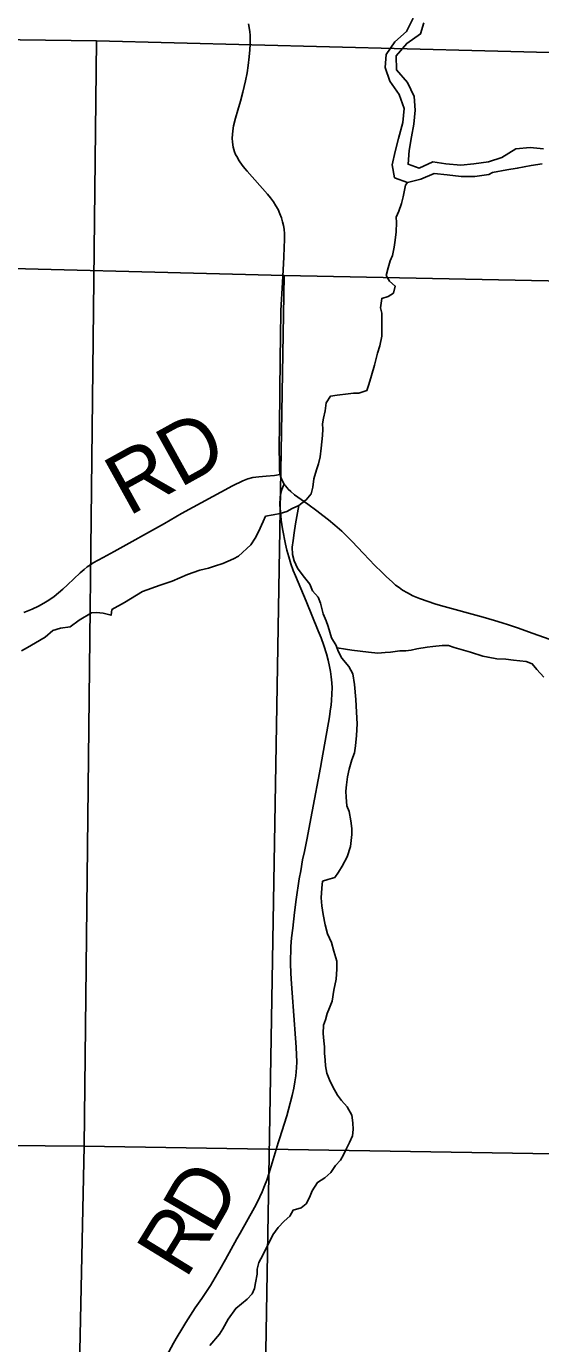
# Model space of a CAD drawing. Extents: x -19.9 to 41.9, y 0 to 32.3.
# Drawn here: x 5.786 to 6.268, y 15.736 to 16.969 of the extents above; entities that cross this region are included whole.
import ezdxf

# ---------------------------------------------------------------- set-up
doc = ezdxf.new("R2010")
doc.units = 0
for name, color, linetype in [('GM_X_Corporation', 7, 'Continuous'), ('GM_X_County_Road', 7, 'Continuous'), ('GM_X_Major_River', 7, 'Continuous'), ('GM_X_Minor_River', 7, 'Continuous'), ('GM_X_Section', 7, 'Continuous'), ('GM_X_Township_Road', 7, 'Continuous'), ('GM_X_Township_Road_Text', 7, 'Continuous')]:
    doc.layers.add(name, color=color, linetype=linetype)

msp = doc.modelspace()

# ---------------------------------------------------------------- linework, layer by layer
at = {"layer": 'GM_X_Corporation'}
for points in [[(5.0171, 16.9663), (5.8519, 16.9554), (5.8404, 15.9209), (5.0026, 15.928), (5.0159, 16.8409)], [(5.8519, 16.9554), (6.8696, 16.9292), (6.8522, 15.9041), (5.8404, 15.9209)], [(5.8404, 15.9209), (5.8188, 14.9036), (4.9872, 14.9075), (5.0009, 15.8404), (5.0026, 15.928)], [(6.8522, 15.9041), (6.8226, 14.894), (5.8188, 14.9036), (5.8404, 15.9209)]]:
    msp.add_lwpolyline(points, close=True, dxfattribs=at)
at = {"layer": 'GM_X_County_Road'}
msp.add_lwpolyline([(5.9943, 16.9715), (5.995, 16.968), (5.9956, 16.9639), (5.9958, 16.9607), (5.9958, 16.9572), (5.9957, 16.9525), (5.9954, 16.9472), (5.9948, 16.9404), (5.9939, 16.9324), (5.993, 16.9257), (5.9914, 16.9182), (5.9889, 16.9074), (5.9866, 16.8989), (5.9843, 16.8906), (5.9821, 16.883), (5.9803, 16.876), (5.9795, 16.8711), (5.9792, 16.8677), (5.9791, 16.8645), (5.9793, 16.8605), (5.98, 16.8561), (5.9804, 16.8539), (5.9811, 16.8516), (5.9822, 16.849), (5.9832, 16.8471), (5.9855, 16.8431), (5.9882, 16.8391), (5.9907, 16.8361), (5.9929, 16.8335), (6.0119, 16.812), (6.0148, 16.8084), (6.0175, 16.8047), (6.0198, 16.8011), (6.0219, 16.7975), (6.0237, 16.7936), (6.0251, 16.7898), (6.0262, 16.7862), (6.027, 16.7826), (6.0275, 16.7791), (6.0278, 16.7749), (6.0279, 16.7693), (6.0276, 16.7622), (6.0273, 16.7531), (6.0261, 16.7294), (6.0246, 16.7032), (6.0241, 16.6775), (6.0239, 16.659), (6.0236, 16.6257), (6.0232, 16.5947), (6.0229, 16.576), (6.0232, 16.5582), (6.0234, 16.5537), (6.0237, 16.5506), (6.0239, 16.5494), (6.0243, 16.5478), (6.0251, 16.5454), (6.0264, 16.5427), (6.0277, 16.5405), (6.0283, 16.5397), (6.029, 16.5388), (6.0305, 16.537), (6.0315, 16.5358), (6.0338, 16.5336), (6.0374, 16.5306), (6.0434, 16.5262), (6.0499, 16.5217), (6.0583, 16.5155), (6.0637, 16.5111), (6.0692, 16.507), (6.0749, 16.5021), (6.0815, 16.4964), (6.0909, 16.4871), (6.102, 16.4755), (6.1124, 16.4645), (6.119, 16.458), (6.1231, 16.4539), (6.1289, 16.4487), (6.1319, 16.446), (6.1351, 16.4436), (6.1383, 16.4414), (6.1429, 16.4387), (6.148, 16.4361), (6.1543, 16.4335), (6.1624, 16.4306), (6.1687, 16.4286), (6.1738, 16.427), (6.214, 16.4159), (6.2192, 16.4145), (6.2246, 16.4129), (6.2317, 16.4107), (6.2377, 16.4087), (6.246, 16.406), (6.2608, 16.4008), (6.2755, 16.3954)], dxfattribs=at)
at = {"layer": 'GM_X_Major_River'}
for points in [[(6.1484, 16.9767), (6.1421, 16.9641), (6.1313, 16.9545), (6.123, 16.9426)], [(6.1327, 16.9283), (6.1325, 16.9416), (6.1423, 16.9531), (6.1551, 16.9619), (6.1584, 16.9722)], [(6.123, 16.9426), (6.122, 16.9304), (6.1264, 16.9176), (6.1353, 16.9052), (6.14, 16.8923), (6.1386, 16.879), (6.1346, 16.8642), (6.1314, 16.852), (6.1288, 16.8395), (6.1309, 16.8273), (6.1431, 16.8229), (6.1556, 16.8261), (6.1681, 16.8312), (6.1802, 16.8302), (6.1932, 16.8285), (6.2061, 16.8286), (6.2193, 16.8303)], [(6.2703, 16.8544), (6.2578, 16.8558), (6.2445, 16.8545), (6.2313, 16.8464), (6.2188, 16.8421), (6.2052, 16.8404), (6.193, 16.8391), (6.179, 16.8404), (6.1668, 16.8422), (6.1539, 16.8363), (6.1436, 16.84), (6.1446, 16.8529), (6.1468, 16.8655), (6.1489, 16.8776), (6.1503, 16.8906), (6.1493, 16.9034), (6.1431, 16.9166), (6.1327, 16.9283)], [(6.2193, 16.8303), (6.2227, 16.8322), (6.236, 16.8347), (6.2458, 16.8363), (6.2587, 16.8387), (6.269, 16.8404)]]:
    msp.add_lwpolyline(points, dxfattribs=at)
at = {"layer": 'GM_X_Minor_River'}
for points in [[(6.1431, 16.8229), (6.1412, 16.8205), (6.1391, 16.8094), (6.1373, 16.8033), (6.1348, 16.796), (6.1326, 16.7903), (6.1327, 16.7854), (6.1324, 16.7766), (6.1314, 16.769), (6.1307, 16.7625), (6.1289, 16.7545), (6.1267, 16.7495), (6.1249, 16.743), (6.1231, 16.7357), (6.1262, 16.7304), (6.1316, 16.7259), (6.1298, 16.7194), (6.1249, 16.7163), (6.1189, 16.7143), (6.1179, 16.7056), (6.1191, 16.7006), (6.1189, 16.6911), (6.119, 16.6789), (6.1173, 16.6701), (6.1151, 16.6632), (6.1122, 16.6518), (6.1093, 16.6422), (6.1068, 16.6338), (6.105, 16.6281), (6.0975, 16.6257), (6.0925, 16.6256), (6.0876, 16.6251), (6.0771, 16.6238), (6.071, 16.623), (6.0669, 16.6165), (6.0659, 16.6092), (6.0645, 16.6023), (6.0634, 16.597), (6.0639, 16.592), (6.0636, 16.5859), (6.0629, 16.5802), (6.0622, 16.5741), (6.0612, 16.5661), (6.0598, 16.5596), (6.058, 16.5539), (6.0555, 16.5455), (6.0544, 16.5378), (6.053, 16.5313), (6.0482, 16.5259), (6.0414, 16.5205), (6.035, 16.5178), (6.0302, 16.515), (6.0238, 16.513), (6.0173, 16.5118), (6.0102, 16.5105), (6.008, 16.5055), (6.0036, 16.496), (6.0006, 16.4898), (5.9965, 16.4837), (5.985, 16.4732), (5.9801, 16.4705), (5.9703, 16.4661), (5.9624, 16.4637), (5.9567, 16.4618), (5.9488, 16.4601), (5.9371, 16.4558), (5.9228, 16.4498), (5.9115, 16.4459), (5.895, 16.4399), (5.8781, 16.4297), (5.8664, 16.4231), (5.8657, 16.4178), (5.8581, 16.4196), (5.8521, 16.4202), (5.8472, 16.4201), (5.8359, 16.4131), (5.8273, 16.4069), (5.8182, 16.4056), (5.811, 16.4036), (5.8039, 16.3974), (5.7949, 16.392), (5.7874, 16.3877), (5.7818, 16.3845)], [(6.0414, 16.5205), (6.0383, 16.5033), (6.0369, 16.4949), (6.0359, 16.4877), (6.0352, 16.4816), (6.0353, 16.4747), (6.0369, 16.4687), (6.04, 16.4619), (6.0454, 16.4547), (6.0516, 16.4468), (6.054, 16.4407), (6.0593, 16.4347), (6.0617, 16.4291), (6.0641, 16.4192), (6.0669, 16.4124), (6.0688, 16.4071), (6.072, 16.3965), (6.0763, 16.3893), (6.0782, 16.384), (6.0817, 16.3776), (6.0883, 16.3697), (6.0918, 16.3629), (6.0935, 16.353), (6.0948, 16.3389), (6.0953, 16.3271), (6.0959, 16.3161), (6.0953, 16.3051), (6.0943, 16.2955), (6.0936, 16.2891), (6.0911, 16.2825), (6.0885, 16.2737), (6.0868, 16.2665), (6.0861, 16.2589), (6.0854, 16.2531), (6.0855, 16.2474), (6.0864, 16.2395), (6.0884, 16.2341), (6.09, 16.2254), (6.0909, 16.2182), (6.0909, 16.2125), (6.0896, 16.2014), (6.0867, 16.1915), (6.0819, 16.183), (6.0786, 16.1773), (6.0749, 16.1723), (6.0685, 16.1703), (6.0636, 16.1687), (6.0629, 16.1622), (6.0623, 16.1531), (6.0628, 16.1458), (6.064, 16.1375), (6.066, 16.128), (6.0681, 16.1196), (6.072, 16.1113), (6.074, 16.1034), (6.0768, 16.0939), (6.0769, 16.0866), (6.0763, 16.0771), (6.0741, 16.0668), (6.0724, 16.0565), (6.0702, 16.0504), (6.068, 16.045), (6.0662, 16.0389), (6.0644, 16.0339), (6.0641, 16.0263), (6.0646, 16.0195), (6.0654, 16.0138), (6.0655, 16.0077), (6.066, 16.0012), (6.0664, 15.9959), (6.0677, 15.9891), (6.07, 15.983), (6.0732, 15.9762), (6.0774, 15.9686), (6.0813, 15.9634), (6.0867, 15.9577), (6.091, 15.9498), (6.0918, 15.9426), (6.0923, 15.9365), (6.0916, 15.9304), (6.0887, 15.9243), (6.0861, 15.9185), (6.0832, 15.9128), (6.0802, 15.9078), (6.0758, 15.9028), (6.0713, 15.8962), (6.0657, 15.8912), (6.0589, 15.8869), (6.0538, 15.8788), (6.0512, 15.8727), (6.0483, 15.8669), (6.0434, 15.8631), (6.0359, 15.8607), (6.0329, 15.8553), (6.0277, 15.8507), (6.0221, 15.8445), (6.0169, 15.8379), (6.0077, 15.8188), (6.004, 15.8119), (6.0022, 15.8057), (6.0023, 15.8008)], [(6.0771, 16.3872), (6.085, 16.386), (6.0911, 16.385), (6.0987, 16.3843), (6.1066, 16.3833), (6.1154, 16.3823), (6.1222, 16.3828), (6.1271, 16.3832), (6.1358, 16.3845), (6.1415, 16.3846), (6.1464, 16.385), (6.1517, 16.3862), (6.1615, 16.3879), (6.1668, 16.3884), (6.1755, 16.3893), (6.1815, 16.3893), (6.1868, 16.3875), (6.2021, 16.3832), (6.2135, 16.3795), (6.2184, 16.3785), (6.2268, 16.3771), (6.2351, 16.3768), (6.2423, 16.3758), (6.254, 16.3744), (6.2598, 16.3722), (6.264, 16.367), (6.2705, 16.3598)], [(6.0023, 15.8008), (6.0009, 15.7928), (5.9998, 15.7874), (5.9976, 15.7824), (5.9931, 15.7774), (5.9823, 15.7689), (5.9752, 15.7589), (5.9701, 15.7497), (5.9671, 15.7447), (5.9582, 15.7343)]]:
    msp.add_lwpolyline(points, dxfattribs=at)
at = {"layer": 'GM_X_Section'}
for points in [[(5.0099, 16.7619), (6.0276, 16.7357), (6.0103, 15.7106), (4.9984, 15.7274)], [(6.0276, 16.7357), (7.0463, 16.7153), (7.0239, 15.7019), (6.0103, 15.7106)]]:
    msp.add_lwpolyline(points, close=True, dxfattribs=at)
at = {"layer": 'GM_X_Township_Road'}
for points in [[(5.7841, 16.4202), (5.7917, 16.4234), (5.7977, 16.4262), (5.8028, 16.429), (5.8073, 16.4318), (5.8125, 16.4353), (5.8165, 16.4389), (5.8204, 16.4422), (5.8247, 16.4464), (5.8367, 16.4575), (5.8404, 16.4607), (5.8434, 16.463), (5.8463, 16.465), (5.849, 16.4667), (5.8582, 16.4718), (5.8685, 16.4774), (5.9156, 16.5038), (5.9316, 16.5129), (5.9794, 16.5388), (5.989, 16.5437), (5.9937, 16.5454), (5.9984, 16.5466), (6.0038, 16.5475), (6.0107, 16.5481), (6.0185, 16.5487), (6.0239, 16.5494)], [(5.9128, 15.7153), (5.9241, 15.7364), (5.9266, 15.7408), (5.9327, 15.7511), (5.9356, 15.7556), (5.9442, 15.7693), (5.9505, 15.7781), (5.9586, 15.7904), (5.9632, 15.7978), (5.9675, 15.8053), (5.9726, 15.8147), (5.9832, 15.8339), (5.9863, 15.8392), (5.9999, 15.8634), (6.0028, 15.8688), (6.0069, 15.8779), (6.0092, 15.8836), (6.0113, 15.8889), (6.0136, 15.8958), (6.0219, 15.924), (6.0231, 15.9276), (6.03, 15.9493), (6.0317, 15.9551), (6.0351, 15.9681), (6.0366, 15.9751), (6.0377, 15.9809), (6.0385, 15.9866), (6.0392, 15.9941), (6.0395, 15.9998), (6.0392, 16.0063), (6.0388, 16.0134), (6.0382, 16.022), (6.0351, 16.0643), (6.0345, 16.0726), (6.034, 16.0823), (6.0336, 16.0922), (6.0338, 16.1077), (6.0345, 16.1157), (6.0356, 16.1247), (6.0374, 16.1394), (6.0389, 16.1517), (6.0418, 16.1709), (6.0431, 16.1784), (6.0448, 16.1887), (6.0465, 16.1966), (6.0488, 16.2075), (6.0538, 16.234), (6.0616, 16.2754), (6.0628, 16.2823), (6.0699, 16.3226), (6.0707, 16.328), (6.0715, 16.3339), (6.0718, 16.338), (6.0723, 16.3443), (6.0724, 16.3497), (6.0722, 16.3545), (6.0717, 16.36), (6.071, 16.3652), (6.0702, 16.3697), (6.0688, 16.3756), (6.0672, 16.3818), (6.0649, 16.3893), (6.0623, 16.3965), (6.0596, 16.4031), (6.0482, 16.431), (6.0381, 16.4548), (6.0361, 16.4598), (6.034, 16.4658), (6.0319, 16.4725), (6.0302, 16.4788), (6.029, 16.4842), (6.026, 16.4986), (6.0249, 16.5067), (6.0241, 16.5145), (6.0237, 16.521), (6.0238, 16.5287), (6.0244, 16.5316), (6.0251, 16.5345), (6.026, 16.5371), (6.0268, 16.5387), (6.0277, 16.5405)]]:
    msp.add_lwpolyline(points, dxfattribs=at)

# ---------------------------------------------------------------- texts
at = {"layer": 'GM_X_Township_Road_Text'}
for s, height, rotation, p in [('RD', 0.05682, 29.0129, (5.8818, 16.5099)), ('D', 0.0568, 60.0324, (5.9607, 15.8367)), ('R', 0.0568, 58.4505, (5.9354, 15.7954))]:
    msp.add_text(s, height=height, rotation=rotation, dxfattribs=at).set_placement(p)

doc.saveas('drawing.dxf')
